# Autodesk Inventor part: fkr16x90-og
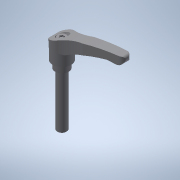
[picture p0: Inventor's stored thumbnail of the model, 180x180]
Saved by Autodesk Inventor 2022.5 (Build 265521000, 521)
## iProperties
Created: 2017-09
Part Number: fkr16x90-og
Material: 一般
Document SubType Name: Modeling
Designer: imaocorp
Density: 1 g/cm^3
Appearance: 既定
Author: imaocorp
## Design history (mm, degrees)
node "fkr16x90-og.x_t1"
node "fkr16x90-og"
node "Base1"
